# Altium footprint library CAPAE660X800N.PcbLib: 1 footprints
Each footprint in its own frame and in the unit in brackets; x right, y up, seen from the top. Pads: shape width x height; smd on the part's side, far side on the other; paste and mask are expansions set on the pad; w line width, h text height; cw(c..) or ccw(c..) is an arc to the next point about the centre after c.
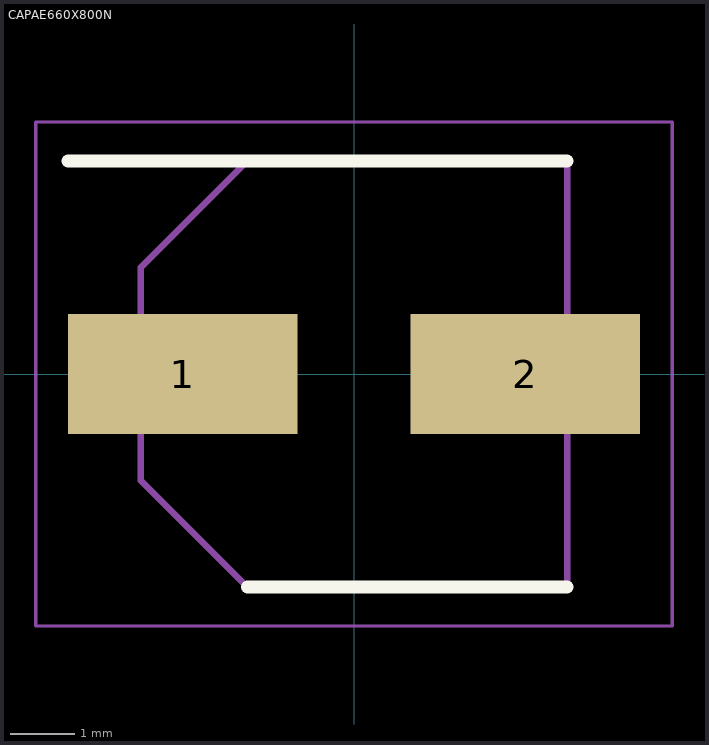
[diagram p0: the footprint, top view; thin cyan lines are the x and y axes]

## CAPAE660X800N [mm]
pads (2):
  rect 3.55x1.85 smd: 1(-2.65,0) 2(2.65,0)
Top Overlay:
  lines w0.2: -4.425,3.3 3.3,3.3 ; -1.65,-3.3 3.3,-3.3
Mechanical 15:
  lines w0.1: -3.3,-1.65 -3.3,1.65 -1.65,3.3 3.3,3.3 3.3,-3.3 -1.65,-3.3 -3.3,-1.65
Mechanical 20:
  lines w0.05: -4.925,-3.9 4.925,-3.9 4.925,3.9 -4.925,3.9 -4.925,-3.9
